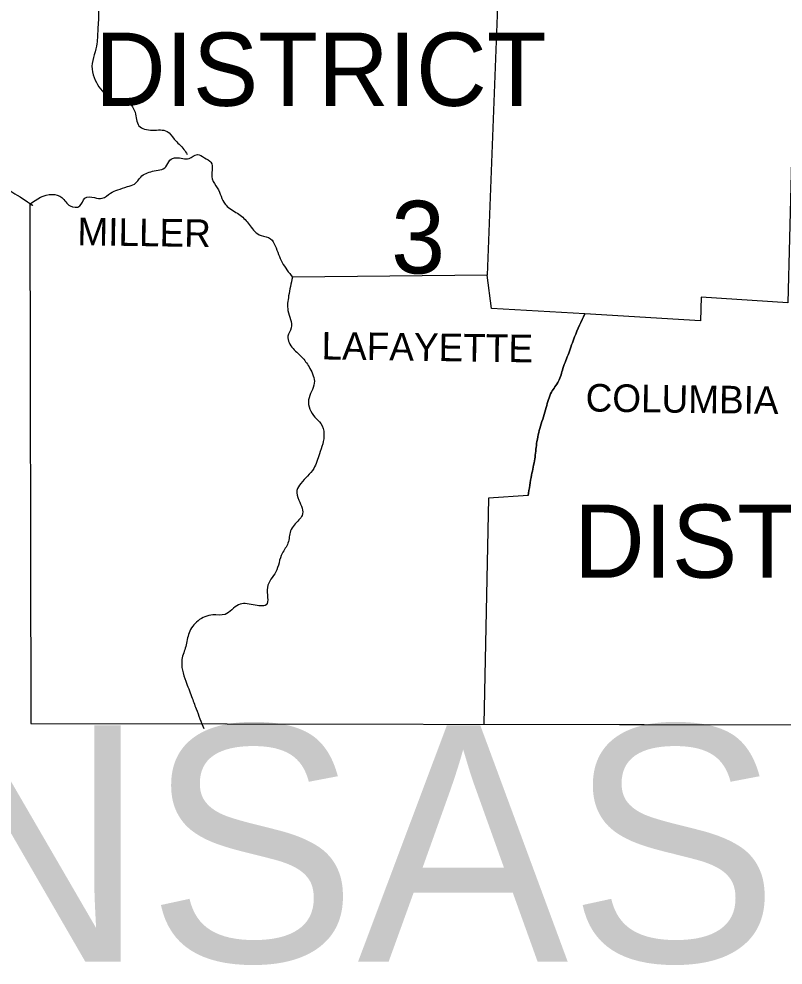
# Model space of a CAD drawing. Extents: x 3046 to 131673, y -8885 to 10756.
# Drawn here: x 102405 to 103569, y 4715 to 6157 of the extents above; entities that cross this region are included whole.
import ezdxf

# ---------------------------------------------------------------- set-up
doc = ezdxf.new("R2010")
doc.units = 0
for name, color, linetype in [('1', 7, 'Continuous'), ('2', 7, 'Continuous'), ('3', 7, 'Continuous'), ('R_Annotation', 7, 'Continuous')]:
    doc.layers.add(name, color=color, linetype=linetype)

msp = doc.modelspace()

# ---------------------------------------------------------------- linework, layer by layer
at = {"layer": '1'}
for points in [[(103157.4, 6478.6), (103155.5, 6283.9), (103137.9, 6282), (103118.3, 5766.3)], [(103157.4, 6478.6), (103155.5, 6283.9), (103137.9, 6282), (103118.3, 5766.3)], [(103588.9, 6217.4), (103576.2, 5724.3), (103444.1, 5733.1), (103443.1, 5696.9), (103267, 5707.6)], [(103588.9, 6217.4), (103576.2, 5724.3), (103444.1, 5733.1), (103443.1, 5696.9), (103267, 5707.6)], [(102421.7, 5874.9), (102423.6, 5083.4), (106009.5, 5077.5)], [(102421.7, 5874.9), (102423.6, 5083.4), (106009.5, 5077.5)], [(103267, 5707.6), (103125.1, 5715.5), (103118.3, 5766.3), (102821.8, 5763.4)], [(103267, 5707.6), (103125.1, 5715.5), (103118.3, 5766.3), (102821.8, 5763.4)], [(103180.9, 5430.7), (103120.2, 5426.8), (103113.4, 5082.4)], [(103180.9, 5430.7), (103120.2, 5426.8), (103113.4, 5082.4)]]:
    msp.add_lwpolyline(points, dxfattribs=at)
for points in [[(102352.2, 6825.9), (102357.1, 6796.6), (102365.9, 6771.2), (102366.9, 6751.6), (102375.7, 6722.2), (102375.7, 6711.5), (102378.6, 6689.9), (102374.7, 6678.2), (102379.6, 6654.7), (102378.6, 6637.1), (102378.6, 6622.4), (102379.6, 6598), (102387.4, 6576.5), (102395.2, 6544.2), (102400.1, 6527.5), (102408, 6502.1), (102412.9, 6470.8), (102413.8, 6447.3), (102411.9, 6425.8), (102417.7, 6401.3), (102428.5, 6376.9), (102442.2, 6353.4), (102458.8, 6327), (102470.6, 6306.4), (102485.3, 6283.9), (102497, 6265.3), (102514.6, 6241.8), (102522.4, 6222.3), (102522.4, 6194.9), (102526.3, 6169.4), (102525.4, 6141.1), (102523.4, 6115.6), (102516.6, 6080.4), (102521.5, 6063.8), (102540, 6039.3), (102551.8, 6032.5), (102572.3, 6028.5), (102582.1, 6014.8), (102588, 5994.3), (102608.5, 5987.5), (102631, 5985.5), (102641.8, 5973.8), (102656.5, 5958.1), (102661.4, 5950.3)], [(102352.2, 6825.9), (102357.1, 6796.6), (102365.9, 6771.2), (102366.9, 6751.6), (102375.7, 6722.2), (102375.7, 6711.5), (102378.6, 6689.9), (102374.7, 6678.2), (102379.6, 6654.7), (102378.6, 6637.1), (102378.6, 6622.4), (102379.6, 6598), (102387.4, 6576.5), (102395.2, 6544.2), (102400.1, 6527.5), (102408, 6502.1), (102412.9, 6470.8), (102413.8, 6447.3), (102411.9, 6425.8), (102417.7, 6401.3), (102428.5, 6376.9), (102442.2, 6353.4), (102458.8, 6327), (102470.6, 6306.4), (102485.3, 6283.9), (102497, 6265.3), (102514.6, 6241.8), (102522.4, 6222.3), (102522.4, 6194.9), (102526.3, 6169.4), (102525.4, 6141.1), (102523.4, 6115.6), (102516.6, 6080.4), (102521.5, 6063.8), (102540, 6039.3), (102551.8, 6032.5), (102572.3, 6028.5), (102582.1, 6014.8), (102588, 5994.3), (102608.5, 5987.5), (102631, 5985.5), (102641.8, 5973.8), (102656.5, 5958.1), (102661.4, 5950.3)], [(101880.6, 6032.5), (101909, 5995.3), (101920.7, 5968.9), (101937.3, 5934.6), (101961.8, 5920.9), (101990.2, 5916), (101996.1, 5882.8), (102025.4, 5881.8), (102048.9, 5888.6), (102081.2, 5879.8), (102115.4, 5903.3), (102135, 5897.4), (102163.4, 5909.2), (102184.9, 5891.6), (102222.1, 5907.2), (102255.3, 5928.7), (102286.6, 5908.2), (102317, 5905.3), (102353.2, 5900.4), (102381.5, 5898.4), (102407, 5885.7), (102425.6, 5873), (102421.7, 5874.9)], [(101880.6, 6032.5), (101909, 5995.3), (101920.7, 5968.9), (101937.3, 5934.6), (101961.8, 5920.9), (101990.2, 5916), (101996.1, 5882.8), (102025.4, 5881.8), (102048.9, 5888.6), (102081.2, 5879.8), (102115.4, 5903.3), (102135, 5897.4), (102163.4, 5909.2), (102184.9, 5891.6), (102222.1, 5907.2), (102255.3, 5928.7), (102286.6, 5908.2), (102317, 5905.3), (102353.2, 5900.4), (102381.5, 5898.4), (102407, 5885.7), (102425.6, 5873), (102421.7, 5874.9)], [(102421.7, 5874.9), (102455.9, 5889.6), (102470.6, 5884.7), (102483.3, 5872), (102498, 5872), (102505.8, 5883.7), (102520.5, 5884.7), (102532.2, 5883.7), (102544.9, 5891.6), (102555.7, 5896.5), (102570.4, 5901.4), (102581.1, 5905.3), (102590.9, 5916), (102608.5, 5924.8), (102629.1, 5931.7), (102635, 5941.5), (102644.7, 5945.4), (102664.3, 5944.4), (102677, 5950.3), (102687.8, 5945.4), (102697.6, 5938.5), (102699.5, 5913.1), (102707.4, 5899.4), (102719.1, 5874.9), (102735.7, 5862.2), (102751.4, 5849.5), (102757.3, 5841.7), (102773.9, 5827), (102788.6, 5822.1), (102795.4, 5811.3), (102806.2, 5785.9), (102821.8, 5763.4)], [(102421.7, 5874.9), (102455.9, 5889.6), (102470.6, 5884.7), (102483.3, 5872), (102498, 5872), (102505.8, 5883.7), (102520.5, 5884.7), (102532.2, 5883.7), (102544.9, 5891.6), (102555.7, 5896.5), (102570.4, 5901.4), (102581.1, 5905.3), (102590.9, 5916), (102608.5, 5924.8), (102629.1, 5931.7), (102635, 5941.5), (102644.7, 5945.4), (102664.3, 5944.4), (102677, 5950.3), (102687.8, 5945.4), (102697.6, 5938.5), (102699.5, 5913.1), (102707.4, 5899.4), (102719.1, 5874.9), (102735.7, 5862.2), (102751.4, 5849.5), (102757.3, 5841.7), (102773.9, 5827), (102788.6, 5822.1), (102795.4, 5811.3), (102806.2, 5785.9), (102821.8, 5763.4)], [(102821.8, 5763.4), (102816, 5735), (102815, 5712.5), (102819.9, 5686.1), (102815, 5673.4), (102822.8, 5654.8), (102837.5, 5640.1), (102848.2, 5624.5), (102855.1, 5602), (102846.3, 5576.5), (102856.1, 5550.1), (102864.9, 5540.3), (102869.8, 5524.7), (102862.9, 5494.3), (102854.1, 5471.8), (102834.5, 5449.3), (102828.7, 5438.6), (102831.6, 5423.9), (102836.5, 5400.4), (102831.6, 5393.6), (102818.9, 5376.9), (102815, 5358.3), (102806.2, 5342.7), (102796.4, 5314.3), (102783.7, 5290.8), (102781.7, 5264.4), (102762.1, 5264.4), (102739.6, 5264.4), (102719.1, 5249.7), (102700.5, 5248.8), (102678, 5239.9), (102664.3, 5221.4), (102659.4, 5200.8), (102653.5, 5181.2), (102659.4, 5148), (102668.2, 5124.5), (102675.1, 5105.9), (102686.8, 5075.6)], [(102821.8, 5763.4), (102816, 5735), (102815, 5712.5), (102819.9, 5686.1), (102815, 5673.4), (102822.8, 5654.8), (102837.5, 5640.1), (102848.2, 5624.5), (102855.1, 5602), (102846.3, 5576.5), (102856.1, 5550.1), (102864.9, 5540.3), (102869.8, 5524.7), (102862.9, 5494.3), (102854.1, 5471.8), (102834.5, 5449.3), (102828.7, 5438.6), (102831.6, 5423.9), (102836.5, 5400.4), (102831.6, 5393.6), (102818.9, 5376.9), (102815, 5358.3), (102806.2, 5342.7), (102796.4, 5314.3), (102783.7, 5290.8), (102781.7, 5264.4), (102762.1, 5264.4), (102739.6, 5264.4), (102719.1, 5249.7), (102700.5, 5248.8), (102678, 5239.9), (102664.3, 5221.4), (102659.4, 5200.8), (102653.5, 5181.2), (102659.4, 5148), (102668.2, 5124.5), (102675.1, 5105.9), (102686.8, 5075.6)], [(103180.9, 5430.7), (103185.8, 5462), (103190.7, 5486.5), (103193.6, 5510), (103199.5, 5536.4), (103208.3, 5564.8), (103216.1, 5588.3), (103226.9, 5604.9), (103233.7, 5624.5), (103242.5, 5647.9), (103251.3, 5672.4), (103267, 5707.6)], [(103180.9, 5430.7), (103185.8, 5462), (103190.7, 5486.5), (103193.6, 5510), (103199.5, 5536.4), (103208.3, 5564.8), (103216.1, 5588.3), (103226.9, 5604.9), (103233.7, 5624.5), (103242.5, 5647.9), (103251.3, 5672.4), (103267, 5707.6)]]:
    msp.add_spline(points, degree=3, dxfattribs=at)
at = {"layer": 'R_Annotation'}
msp.add_line((103113.4, 5082.3), (103740.7, 5081.2), dxfattribs=at)
for points in [[(103576.1, 5724.3), (103444.1, 5733.1), (103443.1, 5696.9), (103267, 5707.6)], [(103180.9, 5430.7), (103120.2, 5426.8), (103113.4, 5082.4)], [(103113.4, 5082.4), (103113.4, 5082.3)]]:
    msp.add_lwpolyline(points, dxfattribs=at)
msp.add_spline([(103267, 5707.6), (103251.3, 5672.4), (103242.5, 5647.9), (103233.7, 5624.5), (103226.9, 5604.9), (103216.1, 5588.3), (103208.3, 5564.8), (103199.5, 5536.4), (103193.6, 5510), (103190.7, 5486.5), (103185.8, 5462), (103180.9, 5430.7)], degree=3, dxfattribs=at)

# ---------------------------------------------------------------- texts
at = {"layer": '2'}
for s, rotation, p in [('MILLER', 359.1319, (102494.1, 5812.3)), ('MILLER', 359.1319, (102494.1, 5812.3)), ('LAFAYETTE', 359.1839, (102865.9, 5638.2)), ('LAFAYETTE', 359.1839, (102865.9, 5638.2)), ('COLUMBIA', 359.2125, (103268, 5558.9)), ('COLUMBIA', 359.2125, (103268, 5558.9))]:
    msp.add_text(s, height=42.06, rotation=rotation, dxfattribs=at).set_placement(p)
msp.add_text('ARKANSAS HIGHWAY DISTRICT 7', height=360, dxfattribs=at).set_placement((100941.1, 4720.5))
at = {"layer": '3'}
for s, height, p in [('DISTRICT', 111.54, (102521, 6024.5)), ('DISTRICT', 111.54, (102521, 6024.5)), ('3', 110.6, (102972, 5769.2)), ('3', 110.6, (102972, 5769.2)), ('DISTRICT 7', 111.54, (103250.4, 5305.5)), ('DISTRICT 7', 111.54, (103250.4, 5305.5))]:
    msp.add_text(s, height=height, dxfattribs=at).set_placement(p)

doc.saveas('drawing.dxf')
